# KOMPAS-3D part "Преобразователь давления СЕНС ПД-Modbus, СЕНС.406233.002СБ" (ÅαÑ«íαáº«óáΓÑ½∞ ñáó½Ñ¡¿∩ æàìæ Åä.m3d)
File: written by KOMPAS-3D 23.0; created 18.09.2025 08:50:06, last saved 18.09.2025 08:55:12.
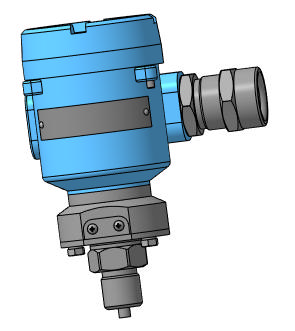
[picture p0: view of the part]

Document properties: Полное имя файла: D:\Рабочая\Изделия\СЕНС ПД\СЕНС ПД-Modbus (2.180)\Для Бирюкова\Преобразователь давления СЕНС ПД.m3d

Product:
- Component: Наконечник 0,5-3-К-ЛТ-03 ГОСТ 22002.6-82  | qty 3  | pos. 1  | Масса: 0.0003; Раздел спецификации: Стандартные изделия; additional columns: Л63 ГОСТ 15527-2004
- Body: Корпус  | designation СЕНС.731142.045-01
    Материал: Сплав АК7 ГОСТ 1583-93 (density 2700 kg/m3)
    Масса: 0.393782
- Body: Втулка  | designation СЕНС.723142.089-01
    Материал: АМг6 ГОСТ 4784-97 (density 2640 kg/m3)
    Масса: 0.106945
- Body: Втулка Д12  | designation СЕНС.713161.058-02
    Масса: 0.096912
- Body: Кольцо уплотнительное D12  | designation СЕНС.754177.041
    Материал: Смесь резиновая АФ-15 ТУ 2512-016-46521402-2004 (density 0 kg/m3)
- Body: Втулка нажимная  | designation СЕНС.711141.350
    Масса: 0.019103
- Body: Втулка резьбовая  | designation СЕНС.713161.059
    Масса: 0.049383
- Body: Шнур резиновый  | designation РР.049.203.119-02
    Материал: Смесь резиновая 54-4084-1Ф ТУ 38.405-51/3-6-263-92 (density 0 kg/m3)
- Body: Кольцо 024-027-19-2 ГОСТ 9833-73
    Материал: Смесь резиновая НО-68-1 ТУ 38 0051166-98 (density 1240 kg/m3)
    Масса: 0.000248
- Body: Кольцо 061-065-25-2-2
    Материал: Смесь резиновая НО-68-1 ТУ 38 0051166-98 (density 1240 kg/m3)
    Масса: 0.001553
- Body: Крышка  | designation СЕНС.711322.031
    Материал: АМг6 ГОСТ 4784-97 (density 2640 kg/m3)
    Масса: 0.111098
- Body: Кольцо 027-030-19-2-2
    Материал: Кольцо 027-030-19-2 ГОСТ 9833-73 (density 0 kg/m3)
- Body: Шайба A.5.01.10.019 ГОСТ 11371-78
    Материал: Сталь 08  ГОСТ 1050-88 (density 7820 kg/m3)
    Масса: 0.000442
- Body: Шайба 5 65Г 019 ГОСТ 6402-70
    Материал: Сталь 65С2ВА  ГОСТ 14959-79 (density 7850 kg/m3)
    Масса: 0.000214
- Body: Болт М5-6gx12.58.019 ГОСТ 7805-70
    Масса: 0.003333
- Body: Hexagon socket set screw ISO 4027 - М4 x 12 - 45H
    Материал: Steel (density 1000 kg/m3)
    Масса: 0.00082
- Body: Штифт 4x8 ГОСТ 3128-70
    Материал: Сталь 45 ГОСТ 1050-88 (density 1000 kg/m3)
    Масса: 0.00078
- Body: Втулка резьбовая  | designation СЕНС.723142.090
    Материал: Шестигранник 36 AISI 321 (density 7850 kg/m3)
    Масса: 0.056045
- Body: Кольцо  | designation СЕНС.711141.459
    Материал: Сталь 12Х18Н10Т ГОСТ 5632-2014 (density 7900 kg/m3)
    Масса: 0.017266
- Body: Заклепка-гайка М3х9-А2
    Материал: Сталь 12Х18Н10Т ГОСТ 5632-2014 (density 7900 kg/m3)
    Масса: 0.000772
- Body: Шайба 3 65Г 019 ГОСТ 6402-70
    Материал: Сталь 65Г ГОСТ 14959-79 (density 1000 kg/m3)
    Масса: 0.000062
- Body: Винт А 2.М 3-6g x 6 ГОСТ 17473-80
    Масса: 0.000474
- Body: Винт А 2.М 3-6g x 6 ГОСТ 17473-80
    Масса: 0.00043
- Body: Кольцо 005-008-19-2
    Материал: Смесь резиновая невулканизированная РС-26ч ТУ 2512-013-46521402-2003 (density 0 kg/m3)
- Body: Шайба  | designation СЕНС.711141.530
    Материал: Сталь 12Х18Н10Т ГОСТ 5632-2014 (density 7900 kg/m3)
    Масса: 0.000326
- Body: Пластина  | designation СЕНС.741124.968
    Материал: Лист 1 AISI 321 (density 7850 kg/m3)
    Масса: 0.001649
- Body: Шайба 2,7 А2 DIN 9021
    Материал: Сталь 12Х18Н10Т ГОСТ 5632-72 (density 1000 kg/m3)
    Масса: 0.000175
- Body: Фильтр  | designation СЕНС.711111.088
    Материал: Мембрана МФФК-4 ТУ 6-55-221-1182-91 (density 0 kg/m3)
- Body: Пластина  | designation СЕНС.741124.971
    Материал: Лист$d1 ГОСТ 19903-2015;12Х18Н10Т ГОСТ 5582-75$ (density 7900 kg/m3)
    Масса: 0.001552
- Body: Тензопреобразователь
    Масса: 0.045187
- Body: Полукольцо  | designation СЕНС.741314.005
    Материал: Лист$d2,0 ГОСТ 19903-74;12Х18Н10Т ГОСТ 5582-75$ (density 7900 kg/m3)
    Масса: 0.012677
- Body: Шпилька приварная M4х12 DIN 13918  | designation Арт.32501.040.16.02
    Материал: Сталь 12Х18Н10Т ГОСТ 5632-2014 (density 7900 kg/m3)
    Масса: 0.00124
- Body: Штуцер  | designation СЕНС.713561.034
    Материал: Сталь 12Х18Н10Т ГОСТ 5632-2014 (density 7900 kg/m3)
    Масса: 0.132733
- Body: Винт DIN 7985  М3x45 - A2
    Масса: 0.002836
- Body: Шайба A.4.01.10.019 ГОСТ 11371-78
    Масса: 0.000308
- Body: Шайба 2 4 ГОСТ 6402-70
    Масса: 0.000126
- Body: Гайка М4-6H.21.12Х18Н10Т ГОСТ 5915-70
    Материал: Сталь 12Х18Н10Т ГОСТ 5632-72 (density 1000 kg/m3)
    Масса: 0.0008
- Body: Табличка  | designation СЕНС.754342.213-01
    Материал: АМц ГОСТ 4784-97 (density 2730 kg/m3)
    Масса: 0.002426
- Body: Заклепка 2x4.37 ГОСТ 10299-80
    Материал: АД1 ГОСТ 4784-97 (density 1000 kg/m3)
    Масса: 0.000053
- Body: Винт ST2,2 x 4,5 - C - H ГОСТ Р ИСО 7049-93
    Масса: 0.000239
- Body: Плата для блока электроники
    Материал: Ф-4 ГОСТ 10007-80 (density 2200 kg/m3)
    Масса: 0.004042
- Body: ptda_1.5-3-3.5
    Масса: 0.019618
- Body: ptda_1.5-3-3.5
    Масса: 0.017113
- Body: 791091009
    Масса: 0.001995
- Body: Наконечник 0,5-3-К-ЛТ-03 ГОСТ 22002.6-82
    Материал: Л63 ГОСТ 15527-2004 (density 1000 kg/m3)
    Масса: 0.0003
- Body: Шайба 5 65Г 019 ГОСТ 6402-70
    Материал: Сталь 65Г ГОСТ 14959-79 (density 1000 kg/m3)
    Масса: 0.000224
- Body: Болт М5-6gx12.58.019 ГОСТ 7805-70
    Масса: 0.003036
- Body: Шайба 5 65Г 019 ГОСТ 6402-70
    Масса: 0.000224
- Body: Болт М5-6gx12.58.019 ГОСТ 7805-70
    Масса: 0.003318
- Body: Кольцо 028-031-19-2 ГОСТ 9833-73
    Материал: Смесь резиновая НО-68-1 ТУ 38 0051166-2015 (density 1240 kg/m3)
    Масса: 0.000341
- Part/product: Преобразователь давления СЕНС ПД-Modbus  | designation СЕНС.406233.002СБ
    Масса: 1.139135

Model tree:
1. Точка:1
     X = -27.1021; Y = 38; Z = 19.6908; Координата X = -27.1021; Координата Y = 38; Координата Z = 19.6908
2. Операция без истории:1
3. Операция без истории:2
4. Операция без истории:3
5. Операция без истории:4
6. Операция без истории:5
7. Операция без истории:6
8. Операция без истории:7
9. Операция без истории:8
10. Операция без истории:9
11. Операция без истории:10
12. Операция без истории:11
13. Операция без истории:12
14. Операция без истории:13
15. Операция без истории:14
16. Операция без истории:15
17. Операция без истории:16
18. Операция без истории:17
19. Операция без истории:18
20. Операция без истории:26
21. Операция без истории:27
22. Операция без истории:28
23. Операция без истории:29
24. Операция без истории:30
25. Операция без истории:31
26. Операция без истории:32
27. Операция без истории:33
28. Операция без истории:34
29. Операция без истории:35
30. Операция без истории:36
31. Операция без истории:37
32. Операция без истории:38
33. Операция без истории:39
34. Операция без истории:40
35. Операция без истории:41
36. Операция без истории:42
37. Операция без истории:43
38. Операция без истории:44
39. Операция без истории:45
40. Операция без истории:46
41. Операция без истории:47
42. Операция без истории:48
43. Операция без истории:49
44. Операция без истории:50
45. Операция без истории:51
46. Операция без истории:52
47. Операция без истории:53
48. Операция без истории:54
49. Операция без истории:55
50. Операция без истории:56
51. Операция без истории:57
52. Операция без истории:58
53. Операция без истории:59
54. Операция без истории:60
55. Операция без истории:61
56. Операция без истории:62
57. Операция без истории:63
58. Операция без истории:64
59. Операция без истории:65
60. Операция без истории:66
61. Операция без истории:67
62. Операция без истории:68  (labels: Сплав АК7 ГОСТ 1583-93; АМг6 ГОСТ 4784-97; Смесь резиновая АФ-15 ТУ 2512-016-46521402-2004)

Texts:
  СЕНС.406233.002
  СЕНС.406233.002 СБ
